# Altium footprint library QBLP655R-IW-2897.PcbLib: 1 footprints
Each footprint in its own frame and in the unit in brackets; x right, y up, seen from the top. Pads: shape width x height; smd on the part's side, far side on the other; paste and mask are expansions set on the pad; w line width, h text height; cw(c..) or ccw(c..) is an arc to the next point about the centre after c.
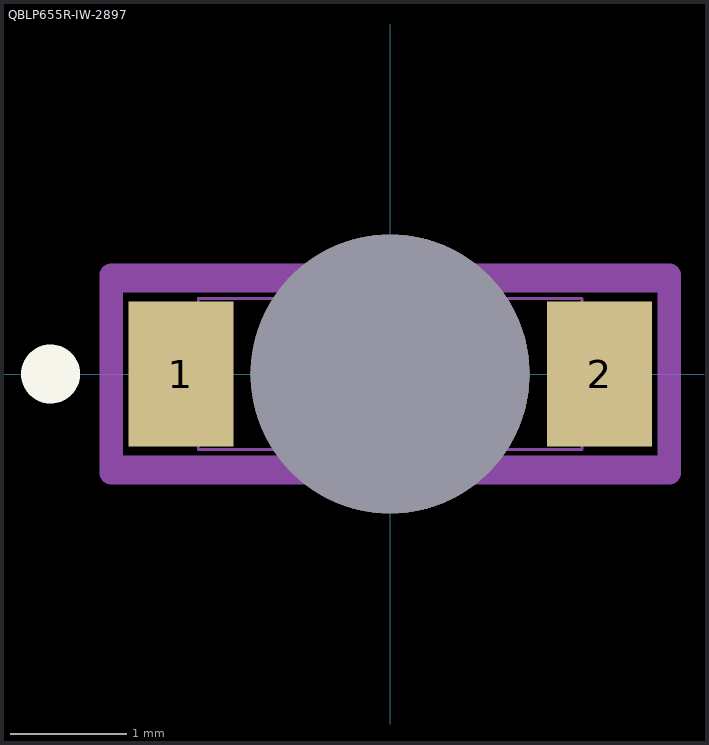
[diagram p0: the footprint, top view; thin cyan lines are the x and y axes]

## QBLP655R-IW-2897 [mm]
pads (3):
  rect 0.9x1.25 smd paste+0 mask+0: 1(-1.8,0) 2(1.8,0)
  round 2.4 hole 2.4 unplated: ""(0,0)
Top Overlay:
  circle w0.254: c-2.921,0 r0.127
  lines w0.152: -0.508,-0.775 0.508,-0.775 ; -0.508,0.775 0.508,0.775
Mechanical 5:
  lines w0.2: -2.4,-0.8 2.4,-0.8 2.4,0.8 -2.4,0.8 -2.4,-0.8
Mechanical 13:
  lines w0.025: -1.651,-0.648 -1.651,0.648 1.651,0.648 1.651,-0.648 -1.651,-0.648
Mechanical 15:
  lines w0.2: -2.4,-0.851 -2.005,-0.851 1.805,-0.851 2.4,-0.851 2.4,0.851 1.805,0.851 -2.005,0.851 -2.4,0.851 -2.4,-0.851
3D body "QBLP655_QBLP655R_MONO.step": height 0.29, standoff -0.81, extent -1.5,-0.6 1.7,0.6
